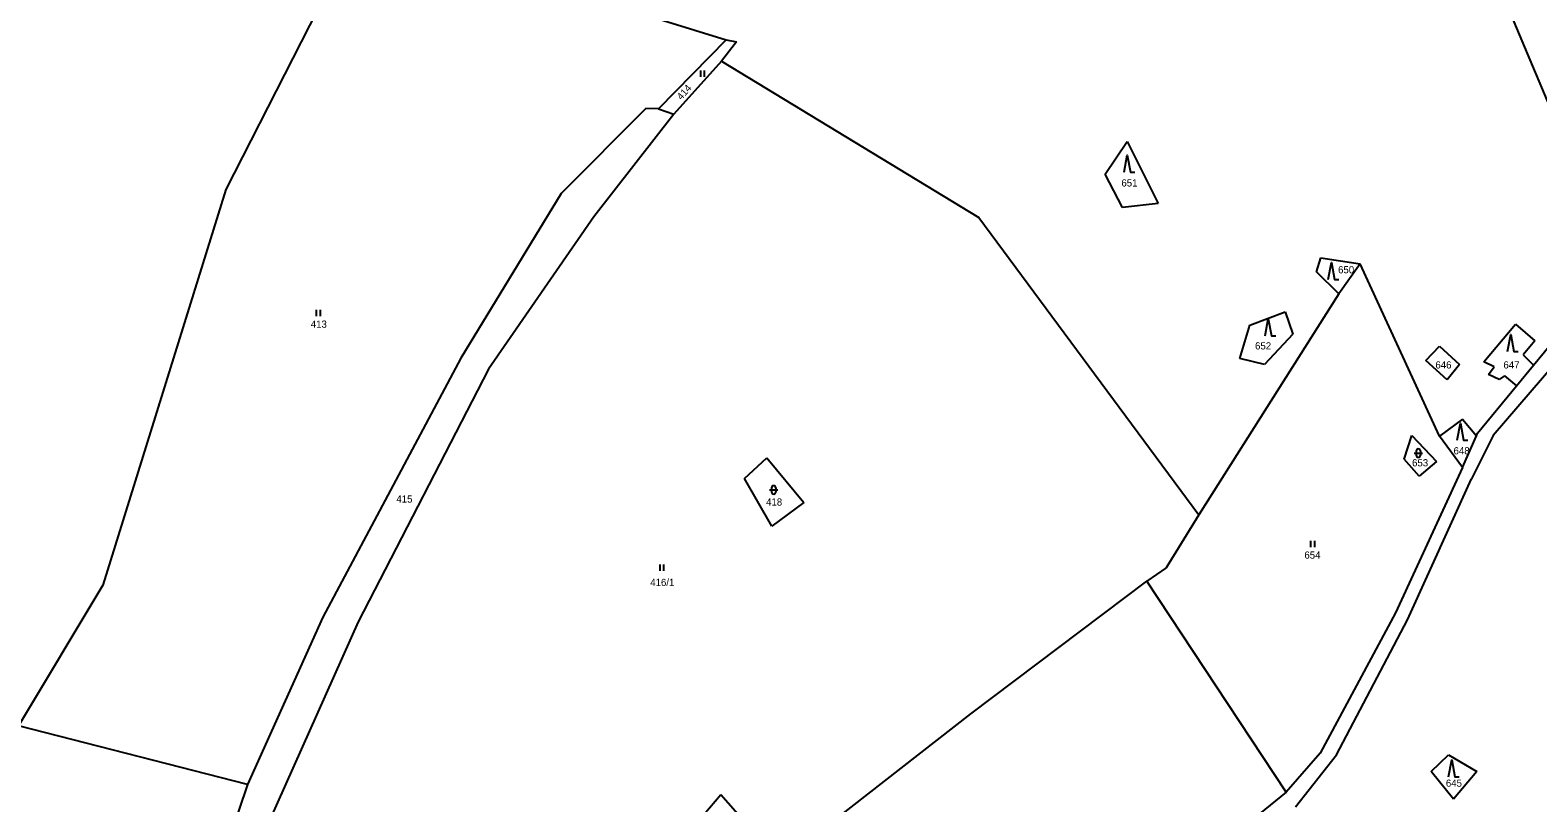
# Model space of a CAD drawing. Extents: x -670359 to -660124, y -978807 to -970072.
# Drawn here: x -668641.1 to -668285.6, y -977581.7 to -977399.4 of the extents above; entities that cross this region are included whole.
import ezdxf

# ---------------------------------------------------------------- set-up
doc = ezdxf.new("R2010")
doc.units = 0
for name, color, linetype in [('Hranice parcel', 7, 'Continuous'), ('Parcelní čísla', 7, 'Continuous'), ('Značky kultur', 7, 'Continuous')]:
    doc.layers.add(name, color=color, linetype=linetype)

msp = doc.modelspace()

# ---------------------------------------------------------------- linework, layer by layer
at = {"layer": 'Hranice parcel'}
for points in [[(-668280.24, -977423.45), (-668302.7, -977370)], [(-668563.4, -977375), (-668594.98, -977437.03)], [(-668563.4, -977375), (-668476.97, -977401.73)], [(-668476.97, -977401.73), (-668493, -977417.97)], [(-668476.97, -977401.73), (-668474.59, -977402.21)], [(-668474.59, -977402.21), (-668478.11, -977406.73)], [(-668478.11, -977406.73), (-668489.36, -977419.22)], [(-668478.11, -977406.73), (-668417.42, -977443.6)], [(-668495.96, -977417.94), (-668515.89, -977437.97)], [(-668489.36, -977419.22), (-668508.24, -977443.44)], [(-668493, -977417.97), (-668495.96, -977417.94)], [(-668493, -977417.97), (-668489.36, -977419.22)], [(-668387.59, -977433.44), (-668382.43, -977425.7)], [(-668382.43, -977425.7), (-668375.1, -977440.36)], [(-668383.54, -977441.27), (-668387.59, -977433.44)], [(-668594.98, -977437.03), (-668623.98, -977530.37)], [(-668515.89, -977437.97), (-668539.61, -977476.83)], [(-668375.1, -977440.36), (-668383.54, -977441.27)], [(-668508.24, -977443.44), (-668533.05, -977479.38)], [(-668417.42, -977443.6), (-668365.52, -977513.77)], [(-668337.79, -977456.48), (-668336.79, -977453.15)], [(-668336.79, -977453.15), (-668327.47, -977454.52)], [(-668327.47, -977454.52), (-668332.52, -977461.63)], [(-668308.8, -977495.19), (-668327.47, -977454.52)], [(-668332.52, -977461.63), (-668337.79, -977456.48)], [(-668332.52, -977461.63), (-668365.52, -977513.77)], [(-668353.53, -977469.05), (-668345.17, -977465.9)], [(-668345.17, -977465.9), (-668343.35, -977471.17)], [(-668269.51, -977464.09), (-668296.09, -977495.03)], [(-668286.58, -977478.47), (-668276.22, -977465.88)], [(-668355.89, -977476.89), (-668353.53, -977469.05)], [(-668298.33, -977477.63), (-668290.89, -977468.77)], [(-668290.89, -977468.77), (-668286.3, -977472.7)], [(-668343.35, -977471.17), (-668350.09, -977478.3)], [(-668286.3, -977472.7), (-668289.07, -977476.04)], [(-668312.02, -977477.39), (-668308.77, -977473.99)], [(-668308.77, -977473.99), (-668304.04, -977478.31)], [(-668289.07, -977476.04), (-668286.58, -977478.47)], [(-668539.61, -977476.83), (-668572.11, -977537.87)], [(-668533.05, -977479.38), (-668563.82, -977538.97)], [(-668350.09, -977478.3), (-668355.89, -977476.89)], [(-668306.97, -977481.89), (-668312.02, -977477.39)], [(-668304.04, -977478.31), (-668306.97, -977481.89)], [(-668295.9, -977478.81), (-668298.33, -977477.63)], [(-668297.2, -977480.68), (-668295.9, -977478.81)], [(-668290.59, -977483.34), (-668286.58, -977478.47)], [(-668299.79, -977494.52), (-668290.59, -977483.34)], [(-668294.72, -977481.84), (-668297.2, -977480.68)], [(-668293.49, -977481.01), (-668294.72, -977481.84)], [(-668293.49, -977481.01), (-668290.59, -977483.34)], [(-668303.38, -977491.22), (-668308.8, -977495.19)], [(-668303.38, -977491.22), (-668300.05, -977495.11)], [(-668300.05, -977495.11), (-668299.79, -977494.52)], [(-668317.08, -977500.66), (-668315.28, -977495.05)], [(-668315.28, -977495.05), (-668309.49, -977501.17)], [(-668303.38, -977502.59), (-668308.8, -977495.19)], [(-668303.38, -977502.59), (-668300.05, -977495.11)], [(-668296.09, -977495.03), (-668301.23, -977505.3)], [(-668472.69, -977505.2), (-668467.4, -977500.34)], [(-668467.4, -977500.34), (-668458.72, -977510.81)], [(-668313.54, -977504.63), (-668317.08, -977500.66)], [(-668309.49, -977501.17), (-668313.54, -977504.63)], [(-668466.2, -977516.39), (-668472.69, -977505.2)], [(-668303.38, -977502.59), (-668319.16, -977536.85)], [(-668316.34, -977538.55), (-668301.23, -977505.3)], [(-668458.72, -977510.81), (-668466.2, -977516.39)], [(-668365.52, -977513.77), (-668373.25, -977526.22)], [(-668373.25, -977526.22), (-668377.84, -977529.42)], [(-668419.28, -977560.69), (-668377.84, -977529.42)], [(-668344.92, -977579.16), (-668377.84, -977529.42)], [(-668623.98, -977530.37), (-668643.87, -977563.55)], [(-668319.16, -977536.85), (-668336.91, -977569.99)], [(-668572.11, -977537.87), (-668589.87, -977577.38)], [(-668563.82, -977538.97), (-668586.71, -977590.44)], [(-668333.08, -977570.37), (-668316.34, -977538.55)], [(-668508.63, -977630.34), (-668419.28, -977560.69)], [(-668589.87, -977577.38), (-668643.87, -977563.55)], [(-668336.91, -977569.99), (-668344.92, -977579.16)], [(-668342.72, -977582.59), (-668333.08, -977570.37)], [(-668310.71, -977574.28), (-668306.65, -977570.34)], [(-668306.65, -977570.34), (-668299.98, -977574.33)], [(-668305.49, -977580.78), (-668310.71, -977574.28)], [(-668299.98, -977574.33), (-668305.49, -977580.78)], [(-668589.87, -977577.38), (-668602.57, -977614.87)], [(-668484.97, -977587.6), (-668478.29, -977579.75)], [(-668478.29, -977579.75), (-668468.51, -977590.82)], [(-668344.92, -977579.16), (-668363.39, -977594.19)]]:
    msp.add_lwpolyline(points, dxfattribs=at)
at = {"layer": 'Značky kultur'}
for p, q in [((-668483.08, -977408.95), (-668483.08, -977410.45)), ((-668482.08, -977410.45), (-668482.08, -977408.95)), ((-668573.68, -977465.43), (-668573.68, -977466.93)), ((-668572.68, -977466.93), (-668572.68, -977465.43)), ((-668314.78, -977499.19), (-668312.78, -977499.19)), ((-668314.28, -977498.69), (-668314.28, -977499.69)), ((-668313.28, -977498.69), (-668313.28, -977499.69)), ((-668466.8, -977507.88), (-668464.8, -977507.88)), ((-668466.3, -977507.38), (-668466.3, -977508.38)), ((-668465.3, -977507.38), (-668465.3, -977508.38)), ((-668339.18, -977519.89), (-668339.18, -977521.39)), ((-668338.18, -977521.39), (-668338.18, -977519.89)), ((-668492.68, -977525.5), (-668492.68, -977527)), ((-668491.68, -977527), (-668491.68, -977525.5))]:
    msp.add_line(p, q, dxfattribs=at)
for points in [[(-668383.17, -977432.93), (-668382.42, -977428.93), (-668381.67, -977432.93), (-668380.67, -977432.93)], [(-668335.03, -977458.26), (-668334.28, -977454.26), (-668333.53, -977458.26), (-668332.53, -977458.26)], [(-668349.91, -977471.54), (-668349.16, -977467.54), (-668348.41, -977471.54), (-668347.41, -977471.54)], [(-668292.72, -977475.25), (-668291.97, -977471.25), (-668291.22, -977475.25), (-668290.22, -977475.25)], [(-668304.6, -977496.11), (-668303.85, -977492.11), (-668303.1, -977496.11), (-668302.1, -977496.11)], [(-668306.66, -977575.57), (-668305.91, -977571.57), (-668305.16, -977575.57), (-668304.16, -977575.57)]]:
    msp.add_lwpolyline(points, dxfattribs=at)
for centre, start, end in [((-668313.78, -977498.69), 0, 180), ((-668313.78, -977499.69), 180, 0), ((-668465.8, -977507.38), 0, 180), ((-668465.8, -977508.38), 180, 0)]:
    msp.add_arc(centre, 0.5, start, end, dxfattribs=at)

# ---------------------------------------------------------------- texts
at = {"layer": 'Parcelní čísla'}
msp.add_text('414', height=1.7, rotation=48.2606, dxfattribs=at).set_placement((-668487.57, -977416.03))
for s, p in [('651', (-668383.8, -977436.32)), ('650', (-668332.7, -977456.79)), ('413', (-668574.97, -977469.63)), ('652', (-668352.28, -977474.75)), ('646', (-668309.75, -977479.24)), ('647', (-668293.71, -977479.24)), ('648', (-668305.47, -977499.49)), ('653', (-668315.25, -977502.33)), ('415', (-668554.78, -977510.87)), ('418', (-668467.59, -977511.58)), ('654', (-668340.64, -977524.09)), ('416/1', (-668494.91, -977530.54)), ('645', (-668307.28, -977577.89))]:
    msp.add_text(s, height=1.7, dxfattribs=at).set_placement(p)

doc.saveas('drawing.dxf')
